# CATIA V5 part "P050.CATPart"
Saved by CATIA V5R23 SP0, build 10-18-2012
Part number: P050
Definition: Graisseur - M6 x 100
Description: Graisseur Lub droit - M6 x 100
Property "REFERENCE": "920 40 02"
Property "SUPPLIER": "TECALEMIT EQUIPEMENTS"
Property "AUTHOR": "Trace Parts S.A."
Property "WEB": "www.traceparts.com"
Bounding box of the stored display mesh (mm): x -3.5 to 3.5, y -5 to 3, z -4.041 to 4.041
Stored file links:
  C:\wamp\www\COURS\CONCEPTION GMP1\TITRE 02-SEMESTRE 2\03-TP7-PRESSE MECANIQUE\eleve\P050.CATPart
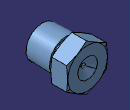
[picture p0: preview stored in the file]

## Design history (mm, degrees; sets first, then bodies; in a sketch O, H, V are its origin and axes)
Body1 (main body)
  Solid1: solid without history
